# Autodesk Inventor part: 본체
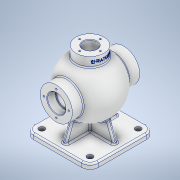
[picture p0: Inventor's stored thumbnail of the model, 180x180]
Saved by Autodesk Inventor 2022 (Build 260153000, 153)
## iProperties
Created: 2024-04
Part Number: 본체
Material: 알루미늄 6061
Document SubType Name: Modeling
Designer: Admin
Density: 2.7 g/cm^3
Appearance: 알루미늄 - 평지
Mass: 1526.72 g
Surface Area: 1173.82 cm^2
Volume: 565.453 cm^3
Author: Admin
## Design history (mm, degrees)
sketch "스케치1"
  geometry: L1 (-54, 0)-(54, 0); A1 r 54 centre (0, 0) between (-54, 0) and (54, 0); 1 further point
  constraints: 2 end point, 2 point on circle, 1 centre point, 1 coincident, 1 horizontal, 1 midpoint
  dimensions: "d0" = 108 diameter of A1
revolve "회전1" sketch "스케치1" stored, may be unused: angle "d1" = 90 deg
node "작업 평면1"
sketch "스케치2"
  geometry: C1 r 31 at (0, 0); 1 further point
  constraints: 1 centre point, 1 coincident
  dimensions: "d3" = 62 diameter of C1
extrude "돌출1" join sketch "스케치2" distance "d4" = 130; taper "d5" = 0 deg
node "작업 평면2"
sketch "스케치3"
  geometry: L1 (62.5, -62.5)-(-62.5, -62.5); L2 (-62.5, -62.5)-(-62.5, 62.5); L3 (-62.5, 62.5)-(62.5, 62.5); L4 (62.5, 62.5)-(62.5, -62.5); L5 (62.5, -62.5)-(-62.5, 62.5); L6 (-62.5, -62.5)-(62.5, 62.5); 1 further point
  constraints: 12 end point, 2 midpoint, 2 parallel, 1 horizontal, 1 perpendicular
  dimensions: "d7" = 125 distance of L2.end L3.end; "d8" = 125 distance of L1.end L2.end
extrude "돌출2" join sketch "스케치3" distance "d9" = 10; taper "d10" = 0 deg
sketch "스케치4"
  geometry: L1 (62.5, -75)-(-62.5, -75) reference; L2 (-50.5, -75)-(-23.202, 0); L3 (-23.202, 0)-(23.202, 0); L4 (23.202, 0)-(50.5, -75); L5 (-62.5, -85)-(-62.5, -75) reference; L6 (62.5, -85)-(62.5, -75) reference; 1 further point
  constraints: 6 end point, 2 point on line, 1 midpoint, 1 parallel
  dimensions: "d11" = 12 distance from line of L5 L2.start; "d12" = 12 distance of L1.start L4.end; "d13" = 20 deg angle of L5 L2; "d14" = 20 deg angle of L6 L4
extrude "돌출3" join sketch "스케치4" stored distance "d15" = 8; taper "d16" = 0 deg
sketch "스케치5"
  geometry: L1 (-75, -62.5)-(-75, 62.5) reference; L2 (-75, 50.5)-(0, 23.202); L3 (0, 23.202)-(0, -23.202); L4 (0, -23.202)-(-75, -50.5); L5 (-75, 50.5)-(-75, -50.5); L6 (-85, 62.5)-(-75, 62.5) reference; L7 (-85, -62.5)-(-75, -62.5) reference; 1 further point
  constraints: 8 end point, 2 point on line, 1 collinear, 1 midpoint, 1 parallel
  dimensions: "d17" = 12 distance from line of L6 L2.start; "d18" = 12 distance from line of L4.end L7; "d19" = 20 deg angle of L6 L2; "d20" = 20 deg angle of L7 L4
extrude "돌출4" join sketch "스케치5" stored distance "d21" = 8; taper "d22" = 0 deg
node "작업 평면3"
sketch "스케치6"
  geometry: C1 r 27 at (0, 0); 1 further point
  constraints: 1 centre point, 1 coincident
  dimensions: "d24" = 54 diameter of C1
extrude "돌출5" join sketch "스케치6" stored distance "d25" = 8; taper "d26" = 0 deg
fillet "모깎기1" dims "d27" = 16
sketch "스케치7"
  geometry: L1 (46.5, 62.5)-(-46.5, 62.5) reference; L2 (62.5, -46.5)-(62.5, 46.5) reference; L3 (-46.5, -62.5)-(46.5, -62.5) reference; L4 (-62.5, 46.5)-(-62.5, -46.5) reference; C1 r 5.5 at (-46.5, -46.5); C2 r 5.5 at (-46.5, 46.5); C3 r 5.5 at (46.5, 46.5); C4 r 5.5 at (46.5, -46.5); A1 r 16 centre (-46.5, 46.5) between (-46.5, 62.5) and (-62.5, 46.5) reference; A2 r 16 centre (46.5, 46.5) between (62.5, 46.5) and (46.5, 62.5) reference; A3 r 16 centre (46.5, -46.5) between (46.5, -62.5) and (62.5, -46.5) reference; A4 r 16 centre (-46.5, -46.5) between (-62.5, -46.5) and (-46.5, -62.5) reference; 1 further point
  constraints: 4 centre point, 4 coincident
  dimensions: "d28" = 11 diameter of C1; "d29" = 11 diameter of C2; "d30" = 11 diameter of C3; "d31" = 11 diameter of C4
extrude "돌출6" cut sketch "스케치7" extent not by distance; stored distance "d32" = 0; taper "d33" = 0 deg
sketch "스케치8"
  geometry: L1 (31, 65)-(-31, 65) reference; L2 (0, 65)-(17.5, 65); L3 (17.5, 65)-(17.5, 49); L4 (17.5, 49)-(0, 49); L5 (0, 49)-(0, 65); L6 (0, 49)-(15, 49); L7 (15, 49)-(15, 41.364); L8 (0, 40.506)-(0, 49); L9 (-31, -65)-(31, -65) reference; L10 (0, -65)-(17.5, -65); L11 (17.5, -65)-(17.5, -49); L12 (17.5, -49)-(0, -49); L13 (0, -49)-(0, -65); L14 (0, -49)-(15, -49); L15 (15, -49)-(15, -41.364); L16 (0, -40.258)-(0, -49); L17 (0, 100.767)-(0, -143.291); A1 r 44 centre (0, 0) between (15, 41.364) and (15, -41.364); 7 further points
  constraints: 30 end point, 6 parallel, 4 horizontal, 4 perpendicular, 3 point on line, 2 midpoint, 2 point on circle, 1 centre point, 1 coincident, 1 vertical
  dimensions: "d34" = 88 diameter of A1; "d35" = 16 distance between parallel lines of L1 L4; "d36" = 16 distance between parallel lines of L10 L12; "d37" = 35 diameter of L3 L17; "d38" = 30 diameter of L7 L17
revolve "회전2" sketch "스케치8" stored, may be unused: angle "d39" = 90 deg
sketch "스케치9"
  geometry: 2 further points
  constraints: 1 vertical alignment
  dimensions: "d40" = 24 distance of point (0, 0) point (0, 24)
hole "구멍1" sketch "스케치9" at (0, 24) diameter "d41" = 3.242; stored, may be unused: countersink angle "d45" = 90 deg, drill point angle "d47" = 118 deg; dims "d42" = 12, "d43" = 4, "d44" = 2, "d46" = 15
sketch "스케치10"
  geometry: C1 r 13 at (0, 0); 1 further point
  constraints: 1 centre point, 1 coincident
  dimensions: "d51" = 26 diameter of C1
extrude "돌출7" cut sketch "스케치10" stored distance "d52" = 10; taper "d53" = 0 deg
fillet "모깎기2" dims "d54" = 3
fillet "모깎기3" dims "d55" = 3
fillet "모깎기4" dims "d56" = 3
fillet "모깎기5" dims "d57" = 3
chamfer "모따기1" distance "d58" = 1; stored, may be unused: second distance "d59" = 2, angle "d60" = 45 deg
chamfer "모따기2" distance "d61" = 1; stored, may be unused: second distance "d62" = 2, angle "d63" = 45 deg
chamfer "모따기3" distance "d64" = 1; stored, may be unused: second distance "d65" = 2, angle "d66" = 45 deg
node "작업 평면4"
sketch "스케치11"
  geometry: L1 (65, -27)-(65, 27) reference; 2 further points
  constraints: 1 horizontal alignment, 1 other
  dimensions: "d68" = 9 distance from line of point (56, 0) L1
feature "엠보싱1" sketch "스케치11" dims "d69" = 0.5, "d70" = 0
sketch "스케치12"
  geometry: 2 further points
  constraints: 1 vertical alignment
  dimensions: "d71" = 20 distance of point (0, 0) point (0, 20)
hole "구멍2" sketch "스케치12" at (0, 20) diameter "d72" = 3.242; stored, may be unused: countersink angle "d76" = 90 deg, drill point angle "d78" = 118 deg; dims "d73" = 9, "d74" = 4, "d75" = 2, "d77" = 11
fillet "모깎기6" dims "d82" = 3
fillet "모깎기7" dims "d83" = 3
fillet "모깎기10" dims "d86" = 0.6
node "솔리드1"
pattern_circular "원형 패턴1" dims angle "d49" = 360 deg
mirror "미러1"
pattern_circular "원형 패턴2" dims angle "d80" = 360 deg
node "투영된 루프1"
feature "A9D066F2-1C7D-4E18-AEED-F7BC21143FA4" dims "d41" = 3.242, "d42" = 12, "d43" = 4, "d44" = 2, "d45" = 90 deg, "d46" = 15, "d47" = 118 deg
other parameters: "d2" = 65, "d6" = -85, "d23" = 65, "d67" = 27
